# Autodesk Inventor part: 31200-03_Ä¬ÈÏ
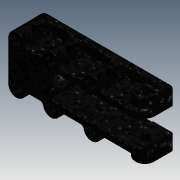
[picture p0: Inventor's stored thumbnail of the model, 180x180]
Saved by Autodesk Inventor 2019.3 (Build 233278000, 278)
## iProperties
Created: 2010-06
Part Number: 31200-03_Ä¬ÈÏ
Material: Ogólny
Document SubType Name: Modeling
Designer: CADENGINEERING4
Density: 1 g/cm^3
Appearance: Czarny
Author: CADENGINEERING4
Revision Number: ÈÎºÎ
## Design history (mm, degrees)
feature "NONE"
node "Bryła1"
